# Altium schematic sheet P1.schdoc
size 600 x 400 mm; Symbol: Drawing-Symbol_A4; Company: 嘉立创EDA; Version: V1.0; Page Size: A4; @Project Name: 大型GB; @Page Count: 1; @Update Date: 2025-11-08; @Create Date: 2025-11-08; @Schematic Name: Schematic1; @Page No: 1; @Page Name: P1; Device: Drawing-Symbol_A4; @Create Time: 14:16:57; @Update Time: 14:16:57; Border: 1; Width: 2362.2047244094488; Height: 1574.8031496062993; Region Start: 1; X Region Count: 6; Y Region Count: 4; Blade Width: 10; Title Block Position: 3; Title Block: 1; @Board Name: Board1
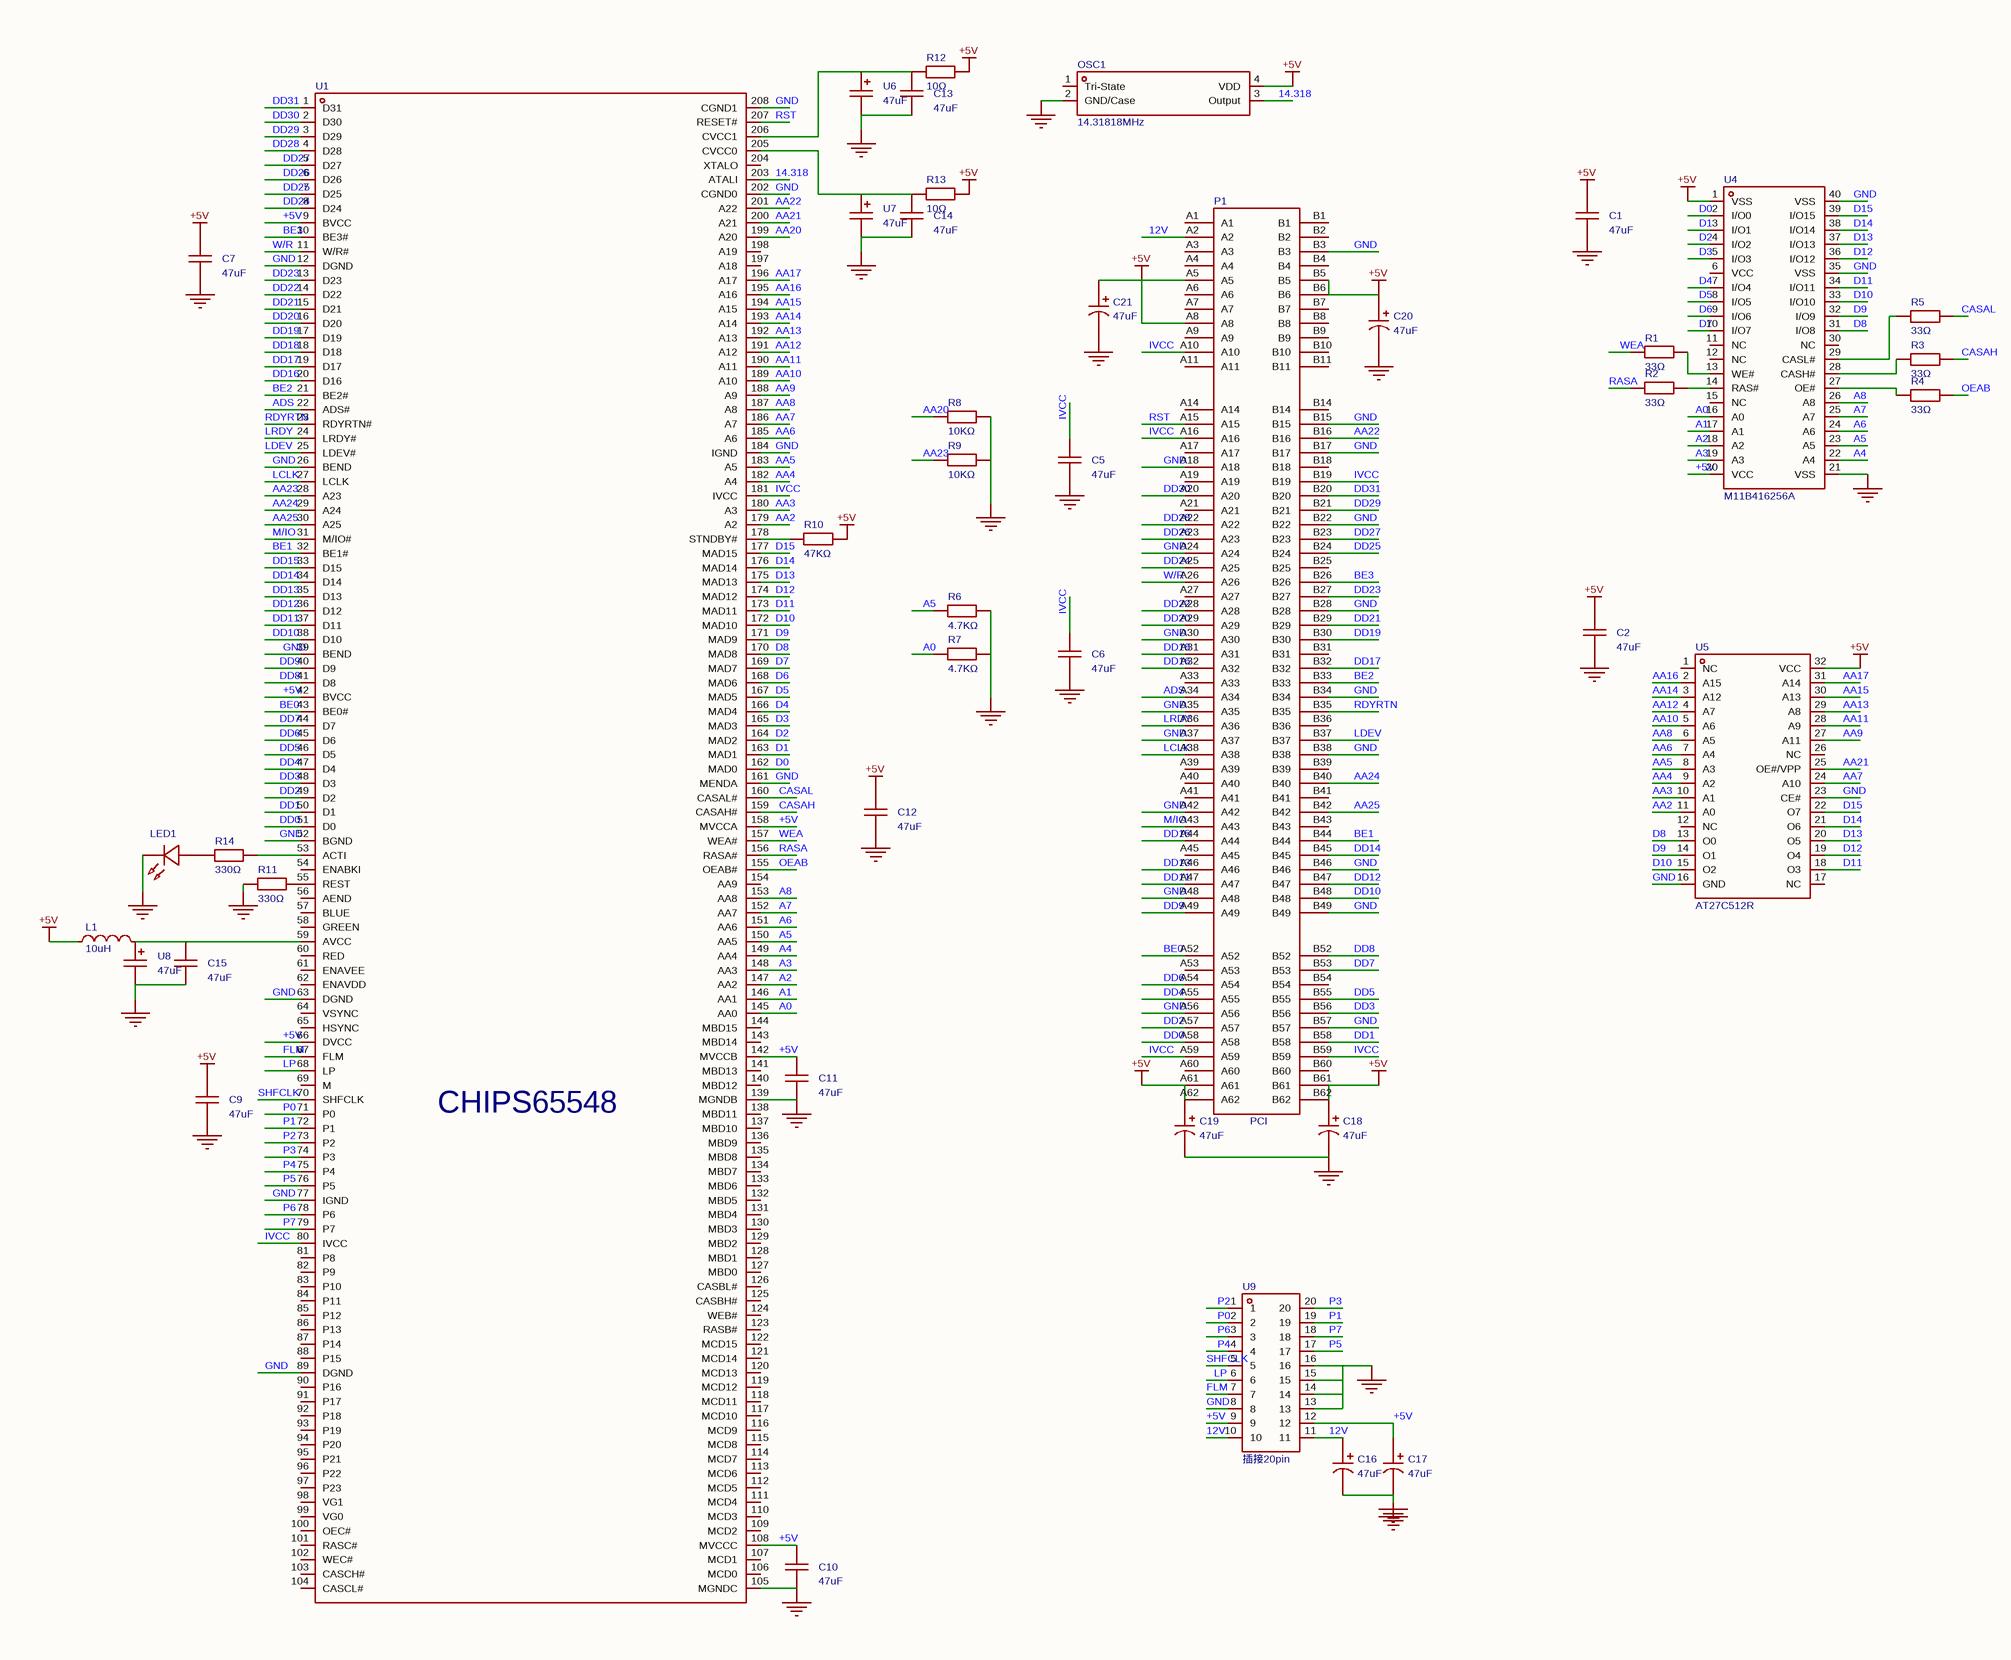
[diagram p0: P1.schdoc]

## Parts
C1  47uF  [C0805]
C2  47uF  [C0805]
C5  47uF  [C0805]
C6  47uF  [C0805]
C7  47uF  [C0805]
C9  47uF  [C0805]
C10  47uF  [C0805]
C11  47uF  [C0805]
C12  47uF  [C0805]
C13  47uF  [C0805]
C14  47uF  [C0805]
C15  47uF  [C0805]
C16  47uF  [CAP-SMD_BD6.3-L6.6-W6.6-LS7.3-FD]
C17  47uF  [CAP-SMD_BD6.3-L6.6-W6.6-LS7.3-FD]
C18  47uF  [CAP-SMD_BD6.3-L6.6-W6.6-LS7.3-FD]
C19  47uF  [CAP-SMD_BD6.3-L6.6-W6.6-LS7.3-FD]
C20  47uF  [CAP-SMD_BD6.3-L6.6-W6.6-LS7.3-FD]
C21  47uF  [CAP-SMD_BD6.3-L6.6-W6.6-LS7.3-FD]
L1  10uH  [L0805]
LED1  (no value)  [LED0805-FD]
OSC1  14.31818MHz  [OSC-SMD_4P-L3.2-W2.5-BL]
P1  PCI  [BUS_PCI-KiCAD]
R1  33Ω  [R0805]
R2  33Ω  [R0805]
R3  33Ω  [R0805]
R4  33Ω  [R0805]
R5  33Ω  [R0805]
R6  4.7KΩ  [R0805]
R7  4.7KΩ  [R0805]
R8  10KΩ  [R0805]
R9  10KΩ  [R0805]
R10  47KΩ  [R0805]
R11  330Ω  [R0805]
R12  10Ω  [R0805]
R13  10Ω  [R0805]
R14  330Ω  [R0805]
U1  CHIPS65548  [PQFP-208_L28.0-W28.0-P0.50-LS30.6-BL]
U4  M11B416256A  [SOJ-40_L26.0-W10.2-P1.27-LS11.2-BL]
U5  AT27C512R  [PLCC-32_L14.0-W11.4-P1.27-LS15.0-T]
U6  47uF  [CAP-SMD_L3.5-W2.8-R-RD]
U7  47uF  [CAP-SMD_L3.5-W2.8-R-RD]
U8  47uF  [CAP-SMD_L3.5-W2.8-R-RD]
U9  插接20pin  [20PIN-2.0MM_2_10]

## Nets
+5V: C1.2 C2.2 C7.2 C9.2 C10.2 C11.2 C12.2 C17.1 C18.1 C19.1 C20.1 C21.1 L1.1 OSC1.4(VDD) P1.A5 P1.A8 P1.A61 P1.A62 P1.B5 P1.B6 P1.B61 P1.B62 R10.2 R12.2 R13.2 U1.9(BVCC) U1.42(BVCC) U1.66(DVCC) U1.108(MVCCC) U1.142(MVCCB) U1.158(MVCCA) U4.1(VSS) U4.20(VCC) U5.32(VCC) U9.9 U9.12
GND: C1.1 C2.1 C5.1 C6.1 C7.1 C9.1 C10.1 C11.1 C12.1 C13.1 C14.1 C15.1 C16.2 C17.2 C18.2 C19.2 C20.2 C21.2 LED1.2(C) OSC1.2(GND/Case) P1.A18 P1.A24 P1.A30 P1.A35 P1.A37 P1.A42 P1.A48 P1.A56 P1.B3 P1.B15 P1.B17 P1.B22 P1.B28 P1.B34 P1.B38 P1.B46 P1.B49 P1.B57 R6.2 R7.2 R8.2 R9.2 R11.1 U1.12(DGND) U1.26(BEND) U1.39(BEND) U1.52(BGND) U1.63(DGND) U1.77(IGND) U1.89(DGND) U1.105(MGNDC) U1.139(MGNDB) U1.161(MENDA) U1.184(IGND) U1.202(CGND0) U1.208(CGND1) U4.21(VSS) U4.35(VSS) U4.40(VSS) U5.16(GND) U5.23(CE#) U6.2 U7.2 U8.2 U9.8 U9.13 U9.14 U9.15 U9.16
12V: C16.1 P1.A2 U9.10 U9.11
14.318: OSC1.3(Output) U1.203(ATALI)
A0: R7.1 U1.145(AA0) U4.16(A0)
A1: U1.146(AA1) U4.17(A1)
A2: U1.147(AA2) U4.18(A2)
A3: U1.148(AA3) U4.19(A3)
A4: U1.149(AA4) U4.22(A4)
A5: R6.1 U1.150(AA5) U4.23(A5)
A6: U1.151(AA6) U4.24(A6)
A7: U1.152(AA7) U4.25(A7)
A8: U1.153(AA8) U4.26(A8)
AA2: U1.179(A2) U5.11(A0)
AA3: U1.180(A3) U5.10(A1)
AA4: U1.182(A4) U5.9(A2)
AA5: U1.183(A5) U5.8(A3)
AA6: U1.185(A6) U5.7(A4)
AA7: U1.186(A7) U5.24(A10)
AA8: U1.187(A8) U5.6(A5)
AA9: U1.188(A9) U5.27(A11)
AA10: U1.189(A10) U5.5(A6)
AA11: U1.190(A11) U5.28(A9)
AA12: U1.191(A12) U5.4(A7)
AA13: U1.192(A13) U5.29(A8)
AA14: U1.193(A14) U5.3(A12)
AA15: U1.194(A15) U5.30(A13)
AA16: U1.195(A16) U5.2(A15)
AA17: U1.196(A17) U5.31(A14)
AA20: R8.1 U1.199(A20)
AA21: U1.200(A21) U5.25(OE#/VPP)
AA22: P1.B16 U1.201(A22)
AA23: R9.1 U1.28(A23)
AA24: P1.B40 U1.29(A24)
AA25: P1.B42 U1.30(A25)
ADS: P1.A34 U1.22(ADS#)
BE0: P1.A52 U1.43(BE0#)
BE1: P1.B44 U1.32(BE1#)
BE2: P1.B33 U1.21(BE2#)
BE3: P1.B26 U1.10(BE3#)
CASAH: R3.2 U1.159(CASAH#)
CASAL: R5.2 U1.160(CASAL#)
D0: U1.162(MAD0) U4.2(I/O0)
D1: U1.163(MAD1) U4.3(I/O1)
D2: U1.164(MAD2) U4.4(I/O2)
D3: U1.165(MAD3) U4.5(I/O3)
D4: U1.166(MAD4) U4.7(I/O4)
D5: U1.167(MAD5) U4.8(I/O5)
D6: U1.168(MAD6) U4.9(I/O6)
D7: U1.169(MAD7) U4.10(I/O7)
D8: U1.170(MAD8) U4.31(I/O8) U5.13(O0)
D9: U1.171(MAD9) U4.32(I/O9) U5.14(O1)
D10: U1.172(MAD10) U4.33(I/O10) U5.15(O2)
D11: U1.173(MAD11) U4.34(I/O11) U5.18(O3)
D12: U1.174(MAD12) U4.36(I/O12) U5.19(O4)
D13: U1.175(MAD13) U4.37(I/O13) U5.20(O5)
D14: U1.176(MAD14) U4.38(I/O14) U5.21(O6)
D15: U1.177(MAD15) U4.39(I/O15) U5.22(O7)
DD0: P1.A58 U1.51(D0)
DD1: P1.B58 U1.50(D1)
DD2: P1.A57 U1.49(D2)
DD3: P1.B56 U1.48(D3)
DD4: P1.A55 U1.47(D4)
DD5: P1.B55 U1.46(D5)
DD6: P1.A54 U1.45(D6)
DD7: P1.B53 U1.44(D7)
DD8: P1.B52 U1.41(D8)
DD9: P1.A49 U1.40(D9)
DD10: P1.B48 U1.38(D10)
DD11: P1.A47 U1.37(D11)
DD12: P1.B47 U1.36(D12)
DD13: P1.A46 U1.35(D13)
DD14: P1.B45 U1.34(D14)
DD15: P1.A44 U1.33(D15)
DD16: P1.A32 U1.20(D16)
DD17: P1.B32 U1.19(D17)
DD18: P1.A31 U1.18(D18)
DD19: P1.B30 U1.17(D19)
DD20: P1.A29 U1.16(D20)
DD21: P1.B29 U1.15(D21)
DD22: P1.A28 U1.14(D22)
DD23: P1.B27 U1.13(D23)
DD24: P1.A25 U1.8(D24)
DD25: P1.B24 U1.7(D25)
DD26: P1.A23 U1.6(D26)
DD27: P1.B23 U1.5(D27)
DD28: P1.A22 U1.4(D28)
DD29: P1.B21 U1.3(D29)
DD30: P1.A20 U1.2(D30)
DD31: P1.B20 U1.1(D31)
FLM: U1.67(FLM) U9.7
IVCC: C5.2 C6.2 P1.A10 P1.A16 P1.A59 P1.B19 P1.B59 U1.80(IVCC) U1.181(IVCC)
LCLK: P1.A38 U1.27(LCLK)
LDEV: P1.B37 U1.25(LDEV#)
LP: U1.68(LP) U9.6
LRDY: P1.A36 U1.24(LRDY#)
M/IO: P1.A43 U1.31(M/IO#)
OEAB: R4.2 U1.155(OEAB#)
P0: U1.71(P0) U9.2
P1: U1.72(P1) U9.19
P2: U1.73(P2) U9.1
P3: U1.74(P3) U9.20
P4: U1.75(P4) U9.4
P5: U1.76(P5) U9.17
P6: U1.78(P6) U9.3
P7: U1.79(P7) U9.18
RASA: R2.1 U1.156(RASA#)
RDYRTN: P1.B35 U1.23(RDYRTN#)
RST: P1.A15 U1.207(RESET#)
SHFCLK: U1.70(SHFCLK) U9.5
W/R: P1.A26 U1.11(W/R#)
WEA: R1.1 U1.157(WEA#)
NetC13_2: C13.2 R12.1 U1.206(CVCC1) U6.1
NetC14_2: C14.2 R13.1 U1.205(CVCC0) U7.1
NetC15_2: C15.2 L1.2 U1.59(AVCC) U8.1
NetLED1_1: LED1.1(A) R14.2
NetR1_2: R1.2 U4.13(WE#)
NetR2_2: R2.2 U4.14(RAS#)
NetR3_1: R3.1 U4.28(CASH#)
NetR4_1: R4.1 U4.27(OE#)
NetR5_1: R5.1 U4.29(CASL#)
NetR10_1: R10.1 U1.178(STNDBY#)
NetR11_2: R11.2 U1.55(REST)
NetR14_1: R14.1 U1.53(ACTI)

Not connected (* = marked no-connect by the designer): OSC1 1(Tri-State); P1 A1 A3 A4 A6 A7 A9 A11 A14 A17 A19 A21 A27 A33 A39 A40 A41 A45 A53 A60 B1 B2 B4 B7 B8 B9 B10 B11 B14 B18 B25 B31 B36 B39 B41 B43 B54 B60; U1 54(ENABKI) 56(AEND) 57(BLUE) 58(GREEN) 60(RED) 61(ENAVEE) 62(ENAVDD) 64(VSYNC) 65(HSYNC) 69(M) 81(P8) 82(P9) 83(P10) 84(P11) 85(P12) 86(P13) 87(P14) 88(P15) 90(P16) 91(P17) 92(P18) 93(P19) 94(P20) 95(P21) 96(P22) 97(P23) 98(VG1) 99(VG0) 100(OEC#) 101(RASC#) 102(WEC#) 103(CASCH#) 104(CASCL#) 106(MCD0) 107(MCD1) 109(MCD2) 110(MCD3) 111(MCD4) 112(MCD5) 113(MCD6) 114(MCD7) 115(MCD8) 116(MCD9) 117(MCD10) 118(MCD11) 119(MCD12) 120(MCD13) 121(MCD14) 122(MCD15) 123(RASB#) 124(WEB#) 125(CASBH#) 126(CASBL#) 127(MBD0) 128(MBD1) 129(MBD2) 130(MBD3) 131(MBD4) 132(MBD5) 133(MBD6) 134(MBD7) 135(MBD8) 136(MBD9) 137(MBD10) 138(MBD11) 140(MBD12) 141(MBD13) 143(MBD14) 144(MBD15) 154(AA9) 197(A18) 198(A19) 204(XTALO); U4 6(VCC) 11(NC) 12(NC) 15(NC) 30(NC); U5 1(NC) 12(NC) 17(NC) 26(NC)

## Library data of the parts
C1 C2 C5-C7 C9-C15 = CL21A476MQYNNNE: 容值:47uF;精度:±20%;额定电压:6.3V;温度系数:X5R;; Manufacturer: SAMSUNG(三星); AddInBom: yes; ModelId: 1ba041120af144c991958decab20d241; ModelName: C0805_L2.0-W1.3-H1.3; ModelTransform: 78.74,51.181,0,0,0,0,0,0.0005,0; Tolerance: ±20%; Voltage Rating: 6.3V; Temperature Coefficient: X5R
C16-C21 = LZ1E470M0606: 容值:47uF;精度:±20%;额定电压:25V;纹波电流:170mA;等效串联电阻(ESR):850mΩ;; Manufacturer: JARSON(伽盛); AddInBom: yes; ModelId: 697a8c63e3274188b68c96045bc3ea1c; ModelTransform: 287.401,259.842,0,180,0,0,0.001,0.001,0; Tolerance: ±20%; Voltage Rating: 25V; Ripple Current: 170mA; Equivalent Series Resistance(ESR): 850mΩ; Lifetime: 2000hrs@105℃
L1 = SDFL2012S100KTF: 电感值:10uH;精度:±10%;额定电流:15mA;饱和电流(Isat):-;直流电阻(DCR):1.15Ω;; Manufacturer: Sunlord(顺络); AddInBom: yes; ModelId: 37a81e68749a4138bd2dfa6897b24b85; ModelName: R0805_L2.0-W1.3-H0.6; ModelTransform: 78.74,51.181,0,0,0,0,0,0.001,0; Tolerance: ±10%; Rated Current: 15mA; DC Resistance(DCR): 1.15Ω
LED1 = GL0805UG01: 灯头类型:-;发光颜色:翠绿色;正向压降(Vf):3.1V;功率:-;正向电流:5mA;波长:510nm~531nm;二极管配置:独立二极管;透镜颜色:无色透明透镜;色温:-;发光强度:299mcd;发光角度:120°;载带方式:正贴;工作温度:-40℃~+85℃;; Manufacturer: Guiguang light(桂光光电); AddInBom: yes; ModelId: 74833d193aea448a9f613f55d84508ab; ModelName: LED0805_Inf; ModelTransform: 78.74,49.213,0,0,0,0,0,0,0; Illumination Color: 翠绿色; Voltage - Forward(Vf): 3.1V; Forward Current: 5mA; Diode Configuration: 独立二极管; Lens Color: 无色透明透镜; Luminous Intensity: 299mcd; Viewing Angle: 120°
OSC1 = ASE-14.31818MHZ-LR-T: 频率:14.31818MHz;输出模式:CMOS;工作电压:3.3V;工作电流:7mA;; Manufacturer: ABRACON; AddInBom: yes; ModelId: ae22b8d143894765bc8100c37cb6356f; ModelName: OSC-SMD_4P-L3.2-W2.5-H1.0; ModelTransform: 125.984,98.425,0,0,0,0,0,0,0; Output Type: CMOS; Voltage - Supply: 3.3V; Current - Supply: 7mA
P1 = PCI: AddInBom: yes
R1-R13 = 0805W8F330JT5E: 电阻类型:厚膜电阻;阻值:33Ω;精度:±1%;功率:125mW;工作电压:150V;温度系数:±200ppm/℃;; Manufacturer: UNI-ROYAL(厚声); AddInBom: yes; ModelId: 37a81e68749a4138bd2dfa6897b24b85; ModelName: R0805_L2.0-W1.3-H0.6; ModelTransform: 78.74,51.181,0,0,0,0,0,-0.0005,0; Tolerance: ±1%; Power(Watts): 125mW; Voltage-Supply(Max): 150V
R14 = 0805W8F330JT5E: 电阻类型:厚膜电阻;阻值:33Ω;精度:±1%;功率:125mW;工作电压:150V;温度系数:±200ppm/℃;; Manufacturer: UNI-ROYAL(厚声); 3D Model: 37a81e68749a4138bd2dfa6897b24b85; 3D Model Transform: 78.74,51.181,0,0,0,0,0,-0.0005,0; Tolerance: ±1%; Power(Watts): 125mW; Voltage-Supply(Max): 150V; AddInBom: yes; ModelName: R0805_L2.0-W1.3-H0.6
U1 = 65545: Symbol: XC3S500E-4PQG208I_6; AddInBom: yes; ModelId: 7f1ece16f77c412593503e5080b2c40fb094d8b171f444e5bfa121276cf5e869; ModelTransform: 1204.722015018463,1204.722015018463,149.60599577605723,0,0,0,0,0,0
U4 = M11B416256A: AddInBom: yes; ModelId: e79e4731ce3943e9908087331a8d3c9b; ModelTransform: 1024.998,439.887,0,0,0,0,0,0,0
U5 = AT27C512R-12JC: Manufacturer: MICROCHIP(美国微芯); AddInBom: yes; ModelId: 9be181142ff44d89b2faf1d842f9263f; ModelTransform: 493.0813,595.4433,0,0,0,0,0,0,0
U6-U8 = T491B476K010AT: 容值:47uF;精度:±10%;额定电压:10V;等效串联电阻(ESR):1Ω@100kHz;; Manufacturer: KEMET(基美); Add into BOM: yes; 3D Model: 0dfcda272f9b43668c6086d3a08712ba; 3D Model Transform: 145.669,110.236,0,180,0,0,0,0,0; Tolerance: ±10%; Voltage Rating: 10V; ModelName: CASE-B_L3.5-W2.8-H1.9
U9 = 20PIN2.0: Symbol: SFP插座-20PINSFP; AddInBom: yes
